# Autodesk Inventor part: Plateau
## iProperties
Created: 2002-05
Part Number: Plateau
Material: Par défaut
Document SubType Name: Modélisation
Designer: Flavien MARTY
Control State: 0
Master: False
Checked Out: False
Shininess: 31.0
Length Units: 11269
Angle Units: 11279
Time Units: 11290
Mass Units: 11283
Length Display Precision: 3
Angle Display Precision: 2
Density: 0.0
Volumn: 0.0
Area: 0.0
PropertySet Name: Model Information
Author: Flavien MARTY
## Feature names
1. Extrusion1
